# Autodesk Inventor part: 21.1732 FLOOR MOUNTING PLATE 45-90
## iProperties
Created: 2007-04
Part Number: 21.1732 FLOOR MOUNTING PLATE 45-90
Material: Aluminum-6061
Document SubType Name: Modeling
Designer: Andy Moles
Density: 2.71 g/cm^3
Author: Andy Moles
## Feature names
1. Extrusion1
2. Extrusion2
